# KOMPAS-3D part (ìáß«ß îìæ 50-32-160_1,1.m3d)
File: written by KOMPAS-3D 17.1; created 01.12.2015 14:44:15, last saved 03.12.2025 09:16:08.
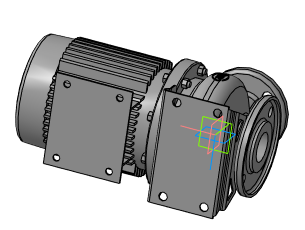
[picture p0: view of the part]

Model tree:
1. Операция без истории:6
